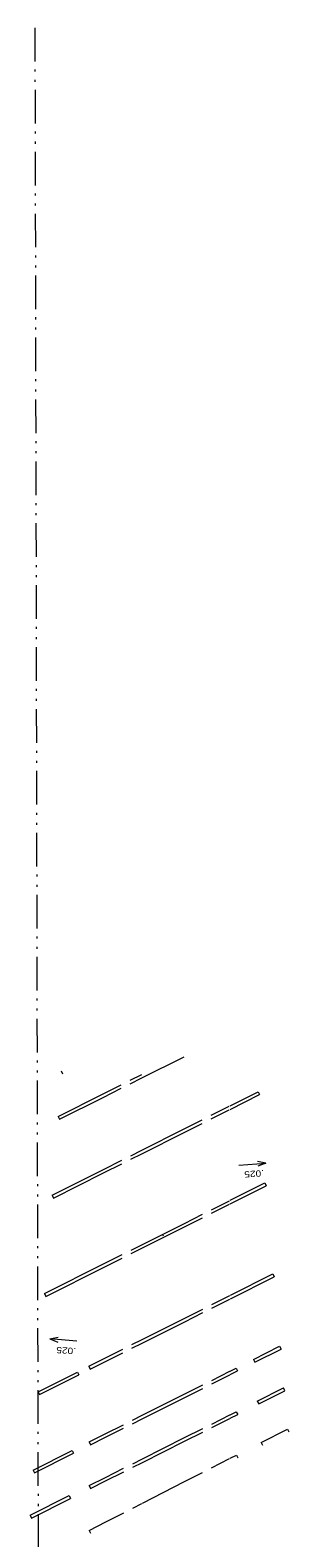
# Model space of a CAD drawing. Extents: x 2356373 to 2371954, y 6966197 to 6989612.
# Drawn here: x 2364243 to 2364488, y 6967166 to 6968599 of the extents above; entities that cross this region are included whole.
import ezdxf

# ---------------------------------------------------------------- set-up
doc = ezdxf.new("R2010")
doc.units = 0
doc.header["$LTSCALE"] = 6.4
doc.linetypes.add('DASH_DOUBLE_DOT', pattern=[9.2, 5, -1.2, 0.3, -1.2, 0.3, -1.2])
doc.linetypes.add('MEDIUM_DASHED', pattern=[4.5, 3, -1.5])
for name, color, linetype, lineweight in [('12', 7, 'Continuous', 13), ('15', 7, 'Continuous', 13), ('19', 7, 'Continuous', 13)]:
    doc.layers.add(name, color=color, linetype=linetype, lineweight=lineweight)

msp = doc.modelspace()

# ---------------------------------------------------------------- linework, layer by layer
at = {"layer": '12'}
for p, q in [((2364348.567, 6967603.085), (2364388.814, 6967623.302)), ((2364271.972, 6967609.755), (2364273.338, 6967607.084)), ((2364269.082, 6967566.514), (2364311.908, 6967588.027)), ((2364270.449, 6967563.844), (2364311.93, 6967584.682)), ((2364432.601, 6967576.604), (2364459.263, 6967590.002)), ((2364432.607, 6967573.25), (2364460.609, 6967587.322)), ((2364459.263, 6967590.002), (2364460.609, 6967587.322)), ((2364269.082, 6967566.514), (2364270.449, 6967563.844)), ((2364348.68, 6967534.433), (2364388.916, 6967554.653)), ((2364348.686, 6967531.078), (2364388.921, 6967551.298)), ((2364263.314, 6967491.535), (2364312.373, 6967516.187)), ((2364264.681, 6967488.864), (2364312.394, 6967512.841)), ((2364432.759, 6967486.771), (2364465.57, 6967503.259)), ((2364432.765, 6967483.416), (2364466.917, 6967500.578)), ((2364465.57, 6967503.259), (2364466.917, 6967500.578)), ((2364263.314, 6967491.535), (2364264.681, 6967488.864)), ((2364348.824, 6967444.592), (2364389.14, 6967464.851)), ((2364348.83, 6967441.238), (2364389.157, 6967461.503)), ((2364368.297, 6967454.178), (2364368.815, 6967453.146)), ((2364256.227, 6967398.06), (2364312.952, 6967426.566)), ((2364257.592, 6967395.39), (2364312.974, 6967423.22)), ((2364432.923, 6967396.592), (2364473.168, 6967416.815)), ((2364432.929, 6967393.238), (2364474.515, 6967414.135)), ((2364473.168, 6967416.815), (2364474.515, 6967414.135)), ((2364256.227, 6967398.06), (2364257.592, 6967395.39)), ((2364348.995, 6967354.417), (2364389.419, 6967374.731)), ((2364349.002, 6967351.063), (2364389.427, 6967371.377)), ((2364298.393, 6967328.988), (2364313.534, 6967336.597)), ((2364454.705, 6967335.452), (2364479.642, 6967347.979)), ((2364454.705, 6967335.452), (2364456.052, 6967332.772)), ((2364456.052, 6967332.772), (2364480.989, 6967345.299)), ((2364479.642, 6967347.979), (2364480.989, 6967345.299)), ((2364250.199, 6967304.77), (2364287.411, 6967323.47)), ((2364251.565, 6967302.099), (2364288.758, 6967320.789)), ((2364287.411, 6967323.47), (2364288.758, 6967320.789)), ((2364298.393, 6967328.988), (2364299.74, 6967326.308)), ((2364299.74, 6967326.308), (2364313.556, 6967333.25)), ((2364432.706, 6967321.044), (2364439.732, 6967324.574)), ((2364432.727, 6967324.412), (2364438.385, 6967327.254)), ((2364438.385, 6967327.254), (2364439.732, 6967324.574)), ((2364458.433, 6967295.805), (2364483.37, 6967308.337)), ((2364484.717, 6967305.657), (2364483.37, 6967308.337)), ((2364250.199, 6967304.77), (2364251.565, 6967302.099)), ((2364349.142, 6967282.423), (2364389.443, 6967302.668)), ((2364349.149, 6967279.071), (2364389.437, 6967299.309)), ((2364458.433, 6967295.805), (2364459.78, 6967293.125)), ((2364459.78, 6967293.125), (2364484.717, 6967305.657)), ((2364432.62, 6967282.835), (2364438.465, 6967285.772)), ((2364432.632, 6967279.484), (2364439.812, 6967283.092)), ((2364438.465, 6967285.772), (2364439.812, 6967283.092)), ((2364298.52, 6967256.994), (2364313.999, 6967264.769)), ((2364462.118, 6967256.506), (2364487.034, 6967269.265)), ((2364487.034, 6967269.265), (2364488.4, 6967266.595)), ((2364245.396, 6967230.308), (2364282.394, 6967248.894)), ((2364282.394, 6967248.894), (2364283.741, 6967246.214)), ((2364298.52, 6967256.994), (2364299.867, 6967254.314)), ((2364299.867, 6967254.314), (2364314.02, 6967261.423)), ((2364349.233, 6967240.931), (2364389.371, 6967261.101)), ((2364349.24, 6967237.578), (2364389.367, 6967257.743)), ((2364462.118, 6967256.506), (2364463.484, 6967253.836)), ((2364246.763, 6967227.638), (2364283.741, 6967246.214)), ((2364432.77, 6967241.48), (2364438.533, 6967244.431)), ((2364438.533, 6967244.431), (2364439.899, 6967241.761)), ((2364245.396, 6967230.308), (2364246.763, 6967227.638)), ((2364298.6, 6967215.487), (2364314.266, 6967223.359)), ((2364299.947, 6967212.807), (2364314.288, 6967220.013)), ((2364242.56, 6967187.327), (2364279.658, 6967205.97)), ((2364279.658, 6967205.97), (2364281.005, 6967203.289)), ((2364298.6, 6967215.487), (2364299.947, 6967212.807)), ((2364349.325, 6967198.753), (2364389.395, 6967219.27)), ((2364369.278, 6967207.284), (2364369.279, 6967207.284)), ((2364243.927, 6967184.656), (2364281.005, 6967203.289)), ((2364242.56, 6967187.327), (2364243.927, 6967184.656)), ((2364298.671, 6967172.816), (2364314.541, 6967180.942)), ((2364298.671, 6967172.816), (2364300.037, 6967170.146))]:
    msp.add_line(p, q, dxfattribs=at)
at = {"layer": '12', "linetype": 'MEDIUM_DASHED'}
for p, q in [((2364311.908, 6967588.027), (2364348.561, 6967606.439)), ((2364311.93, 6967584.681), (2364348.567, 6967603.085)), ((2364388.916, 6967554.653), (2364432.601, 6967576.605)), ((2364388.921, 6967551.297), (2364432.607, 6967573.25)), ((2364312.373, 6967516.188), (2364348.68, 6967534.433)), ((2364312.394, 6967512.841), (2364348.686, 6967531.078)), ((2364389.14, 6967464.851), (2364432.759, 6967486.771)), ((2364389.157, 6967461.502), (2364432.765, 6967483.417)), ((2364312.952, 6967426.567), (2364348.824, 6967444.593)), ((2364312.974, 6967423.221), (2364348.83, 6967441.239)), ((2364389.419, 6967374.73), (2364432.923, 6967396.592)), ((2364389.427, 6967371.376), (2364432.929, 6967393.237)), ((2364313.534, 6967336.597), (2364348.995, 6967354.416)), ((2364313.556, 6967333.251), (2364349.002, 6967351.064)), ((2364389.437, 6967299.309), (2364432.706, 6967321.044)), ((2364389.443, 6967302.669), (2364432.727, 6967324.412)), ((2364313.999, 6967264.77), (2364349.142, 6967282.424)), ((2364314.02, 6967261.424), (2364349.149, 6967279.07)), ((2364389.367, 6967257.743), (2364432.632, 6967279.484)), ((2364389.371, 6967261.101), (2364432.62, 6967282.834)), ((2364314.266, 6967223.36), (2364349.233, 6967240.931)), ((2364314.288, 6967220.014), (2364349.24, 6967237.579)), ((2364389.395, 6967219.27), (2364432.77, 6967241.48)), ((2364314.541, 6967180.942), (2364348.531, 6967198.346))]:
    msp.add_line(p, q, dxfattribs=at)
at = {"layer": '15', "linetype": 'DASH_DOUBLE_DOT'}
msp.add_line((2364251.572, 6966626.517), (2364246.452, 6969018.362), dxfattribs=at)
at = {"layer": '19'}
for p, q in [((2364466.693, 6967522.065), (2364458.873, 6967519.246)), ((2364261.142, 6967354.953), (2364269.303, 6967356.535))]:
    msp.add_line(p, q, dxfattribs=at)
for points in [[(2364440.969, 6967520.301), (2364466.693, 6967522.065), (2364458.567, 6967523.789)], [(2364286.832, 6967352.738), (2364261.142, 6967354.953), (2364268.907, 6967351.999)]]:
    msp.add_lwpolyline(points, dxfattribs=at)

# ---------------------------------------------------------------- texts
at = {"layer": '19', "width": 1.2}
for height, rotation, p in [(5.999, 183.797, (2364464.576, 6967515.572)), (6, 175.978, (2364286.322, 6967346.233))]:
    msp.add_text('.025', height=height, rotation=rotation, dxfattribs=at).set_placement(p)

doc.saveas('drawing.dxf')
